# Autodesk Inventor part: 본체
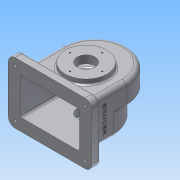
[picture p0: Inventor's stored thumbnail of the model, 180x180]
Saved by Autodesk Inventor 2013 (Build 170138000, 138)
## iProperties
Created: 2017-11
Part Number: 본체
Material: 알루미늄 6061
Document SubType Name: Modeling
Designer: Administrator
Density: 2.71 g/cm^3
Mass: 1097.92 g
Surface Area: 1195.3 cm^2
Volume: 405.135 cm^3
Author: Administrator
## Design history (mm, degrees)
sketch "스케치1" dims "d4" = 58
  geometry: L1 (-58, 15)-(58, 15); L2 (58, 15)-(58, -65); L3 (58, -65)-(-58, -65); L4 (-58, -65)-(-58, 15); 3 further points
  constraints: 8 end point, 2 parallel, 2 vertical alignment, 1 horizontal, 1 horizontal alignment, 1 midpoint, 1 perpendicular, 2 other
  dimensions: "d1" = 116 distance of L2.end L3.end; "d2" = 80 distance of L1.end L2.end; "d3" = 65 distance from line of L3 point (0, 0)
extrude "돌출1" new body sketch "스케치1" distance "d5" = 38; taper "d6" = 0 deg
sketch "스케치2"
  geometry: L1 (-58, 15)-(-58, -65) reference; L2 (-58, -65)-(58, -65) reference; L3 (-58, -8)-(58, -8); L4 (58, -8)-(58, -65); L5 (58, -65)-(-58, -65); L6 (-58, -65)-(-58, -8); A1 r 58 centre (0, -8) between (58, -8) and (-58, -8); 1 further point
  constraints: 8 end point, 2 parallel, 2 point on circle, 1 centre point, 1 horizontal, 1 midpoint, 1 perpendicular, 1 point on line
  dimensions: "d7" = 57 distance between parallel lines of L2 L3
extrude "돌출2" join sketch "스케치2" distance "d8" = 38; taper "d9" = 0 deg
feature "쉘1" dims "d34" = 5
sketch "스케치3"
  geometry: C1 r 37.5 at (0, 0); 1 further point
  constraints: 1 centre point, 1 coincident
  dimensions: "d10" = 75 diameter of C1
extrude "돌출3" join sketch "스케치3" distance "d11" = 9; taper "d12" = 0 deg
sketch "스케치4"
  geometry: C1 r 31 at (0, 0); 1 further point
  constraints: 1 centre point, 1 coincident
  dimensions: "d13" = 62 diameter of C1
extrude "돌출4" join sketch "스케치4" distance "d14" = 10; taper "d15" = 0 deg
sketch "스케치5"
  geometry: L1 (116, 0)-(116, -76) reference; L2 (0, 0)-(116, 0) reference; L3 (0, 0)-(0, -76) reference; L4 (116, -76)-(0, -76) reference; L5 (-17, 17)-(133, 17); L6 (133, 17)-(133, -93); L7 (133, -93)-(-17, -93); L8 (-17, -93)-(-17, 17); L9 (-17, 17)-(133, -93); L10 (133, 17)-(-17, -93); 1 further point
  constraints: 12 end point, 2 midpoint, 2 parallel, 1 horizontal, 1 perpendicular
  dimensions: "d16" = 150 distance of L6.end L7.end; "d17" = 110 distance of L5.end L6.end
extrude "돌출5" join sketch "스케치5" distance "d18" = 15; taper "d19" = 0 deg
sketch "스케치6"
  geometry: C1 r 37.5 at (0, 0) reference; C2 r 16 at (0, 0)
  constraints: 1 centre point, 1 coincident
  dimensions: "d20" = 32 diameter of C2
extrude "돌출6" cut sketch "스케치6" stored distance "d21" = 15; taper "d22" = 0 deg
fillet "모깎기1" dims "d23" = 12
sketch "스케치7"
  geometry: A1 r 12 centre (-5, -5) between (-17, -5) and (-5, -17) reference; A2 r 12 centre (121, -5) between (121, -17) and (133, -5) reference; A3 r 12 centre (121, 81) between (133, 81) and (121, 93) reference; A4 r 12 centre (-5, 81) between (-5, 93) and (-17, 81) reference; 5 further points
  constraints: 4 coincident
hole "구멍1" sketch "스케치7" at (-5, -5), (-5, 81), (121, 81), (121, -5) diameter "d24" = 5; stored, may be unused: countersink angle "d28" = 90 deg, drill point angle "d30" = 118 deg; dims "d25" = 6, "d26" = 12, "d27" = 5, "d29" = 8
fillet "모깎기2" dims "d31" = 3, "d76" = 8
fillet "모깎기3" dims "d32" = 3
sketch "스케치9"
  geometry: C1 r 16 at (0, 0) reference; 1 further point
  constraints: 1 vertical alignment
  dimensions: "d35" = 29 distance of C1.centre point (0, 29)
hole "구멍2" sketch "스케치9" at (0, 29) diameter "d36" = 2.459; stored, may be unused: countersink angle "d40" = 90 deg, drill point angle "d42" = 118 deg; dims "d37" = 6, "d38" = 12, "d39" = 5, "d41" = 8
sketch "스케치10"
  geometry: C1 r 16 at (0, 0) reference; 1 further point
  constraints: 1 vertical alignment
  dimensions: "d43" = 26 distance of C1.centre point (0, 26)
hole "구멍3" sketch "스케치10" at (0, 26) diameter "d44" = 2.459; stored, may be unused: countersink angle "d48" = 90 deg, drill point angle "d50" = 118 deg; dims "d45" = 6, "d46" = 12, "d47" = 5, "d49" = 8
node "작업 평면1"
sketch "스케치11"
  geometry: L1 (-113, 93)-(-13, 93) reference; C1 r 6 at (-63, 74); 1 further point
  constraints: 1 centre point, 1 vertical alignment
  dimensions: "d55" = 12 diameter of C1; "d57" = 19 distance from line of C1.centre L1
extrude "돌출7" join sketch "스케치11" stored distance "d58" = 5; taper "d59" = 0 deg
hole "구멍4" diameter "d62" = 4.459; stored, may be unused: countersink angle "d66" = 90 deg, drill point angle "d68" = 118 deg; dims "d63" = 6, "d64" = 12, "d65" = 5, "d67" = 8, "d69" = 10, "d70" = 10
fillet "모깎기4" dims "d71" = 3
sketch "스케치12"
  geometry: L1 (-35, 23)-(-35, -39) reference; L2 (-40, -57)-(46, -57) reference; 2 further points
  constraints: 1 other
  dimensions: "d72" = 38 distance from line of L1 point (3, -17); "d73" = 40 distance from line of L2 point (3, -17)
feature "엠보싱1" sketch "스케치12" dims "d1" = 116, "d2" = 80, "d3" = 65, "d4" = 58, "d10" = 75, "d74" = 0.5, "d75" = 0
node "솔리드1"
pattern_circular "원형 패턴1" dims angle "d52" = 360 deg
other parameters: "d54" = -144
